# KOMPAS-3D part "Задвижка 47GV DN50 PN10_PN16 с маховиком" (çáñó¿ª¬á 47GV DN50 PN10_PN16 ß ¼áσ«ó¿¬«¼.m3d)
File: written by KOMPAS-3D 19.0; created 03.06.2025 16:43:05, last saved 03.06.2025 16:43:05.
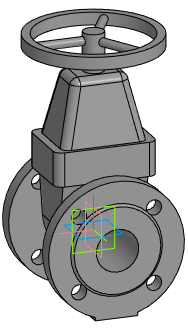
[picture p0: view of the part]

Document properties: Автор: Евгений; Полное имя файла: E:\Dendor Работа Сачек\3D для проекитирвщиков\2.1 Тип 47GV, 47GV.Z Задвижка клиновая фланцевая с обрезиненным клином\stp_Тип 47GV. Задвижка DN40-DN350 с маховиком\Задвижка 47GV DN50 PN10_PN16 с маховиком.m3d

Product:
- Part/product: Задвижка 47GV DN50 PN10_PN16 с маховиком

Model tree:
1. Операция без истории:1  (labels: Задвижка 47GV DN50 PN10_PN16 с маховиком)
